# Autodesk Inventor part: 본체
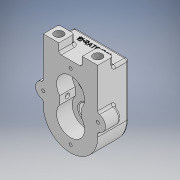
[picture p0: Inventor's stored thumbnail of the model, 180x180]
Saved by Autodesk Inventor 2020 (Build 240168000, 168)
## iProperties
Created: 2024-03
Part Number: 본체
Material: 일반
Document SubType Name: Modeling
Designer: 1강의실14
Density: 1 g/cm^3
Appearance: 기본값
Mass: 238.18 g
Surface Area: 392.046 cm^2
Volume: 238.18 cm^3
Author: 1강의실14
## Parameters: d2 = 136 mm, d4 = 0, d7 = 12 mm, d8 = 0, d9 = 63.5 mm, d12 = 0, d13 = 33 mm, d14 = 52 mm, d15 = 6 mm, d16 = 0, d17 = 32 mm, d18 = 4 mm, d19 = 0, d20 = 33 mm, d21 = 36 mm, d22 = 6 mm, d23 = 4 mm, d24 = 2 mm, d25 = 90 deg, d27 = 0, d28 = 18 mm, d29 = 28 mm, d30 = 16 mm, d32 = 0, d34 = 6 mm, d35 = 4 mm, d36 = 2 mm, d37 = 90 deg, d39 = 0, d40 = 1 mm, d41 = 2 mm, d42 = 45 deg, d43 = 14 mm, d45 = -60 deg, d46 = 15 mm, d47 = 6 mm, d48 = 4 mm, d49 = 2 mm, d50 = 90 deg, d51 = 12.7 mm, d52 = 0, d53 = 25 mm, d54 = 6 mm, d55 = 4 mm, d56 = 2 mm, d57 = 90 deg, d58 = 6.6 mm, d59 = 0, d60 = -49.3 mm, d61 = 25 mm, d62 = 0.7 mm, d63 = 30 deg, d64 = 21 mm, d65 = 3.242 mm, d66 = 8 mm, d67 = 4 mm, d68 = 2 mm, d69 = 90 deg, d71 = 118 deg, d73 = 360 deg, d75 = 26 mm, d76 = 26 mm, d77 = 4.134 mm, d79 = 4 mm, d80 = 2 mm, d81 = 90 deg, d82 = 12 mm, d83 = 118 deg, d84 = 4.134 mm, d86 = 4 mm, d87 = 2 mm, d88 = 90 deg, d89 = 12 mm, d90 = 118 deg, d109 = 6 mm, d111 = 55.5 mm, d112 = 8 mm, d113 = 90 deg, d115 = 6 mm, d116 = 0, d117 = 0, d118 = 0, d119 = 0, d120 = 10.5 mm, d121 = 11 mm, d122 = 0.62479 mm, d123 = 10.589 mm, d124 = 4 mm, d125 = 2 mm, d126 = 90 deg, d127 = 16 mm, d128 = 118 deg, d129 = 3 mm, d130 = 3 mm, d131 = 3 mm, d132 = 3 mm, d133 = 3 mm, d135 = 0.5 mm, d136 = 0, d137 = 1 mm, d138 = 2 mm, d139 = 45 deg
